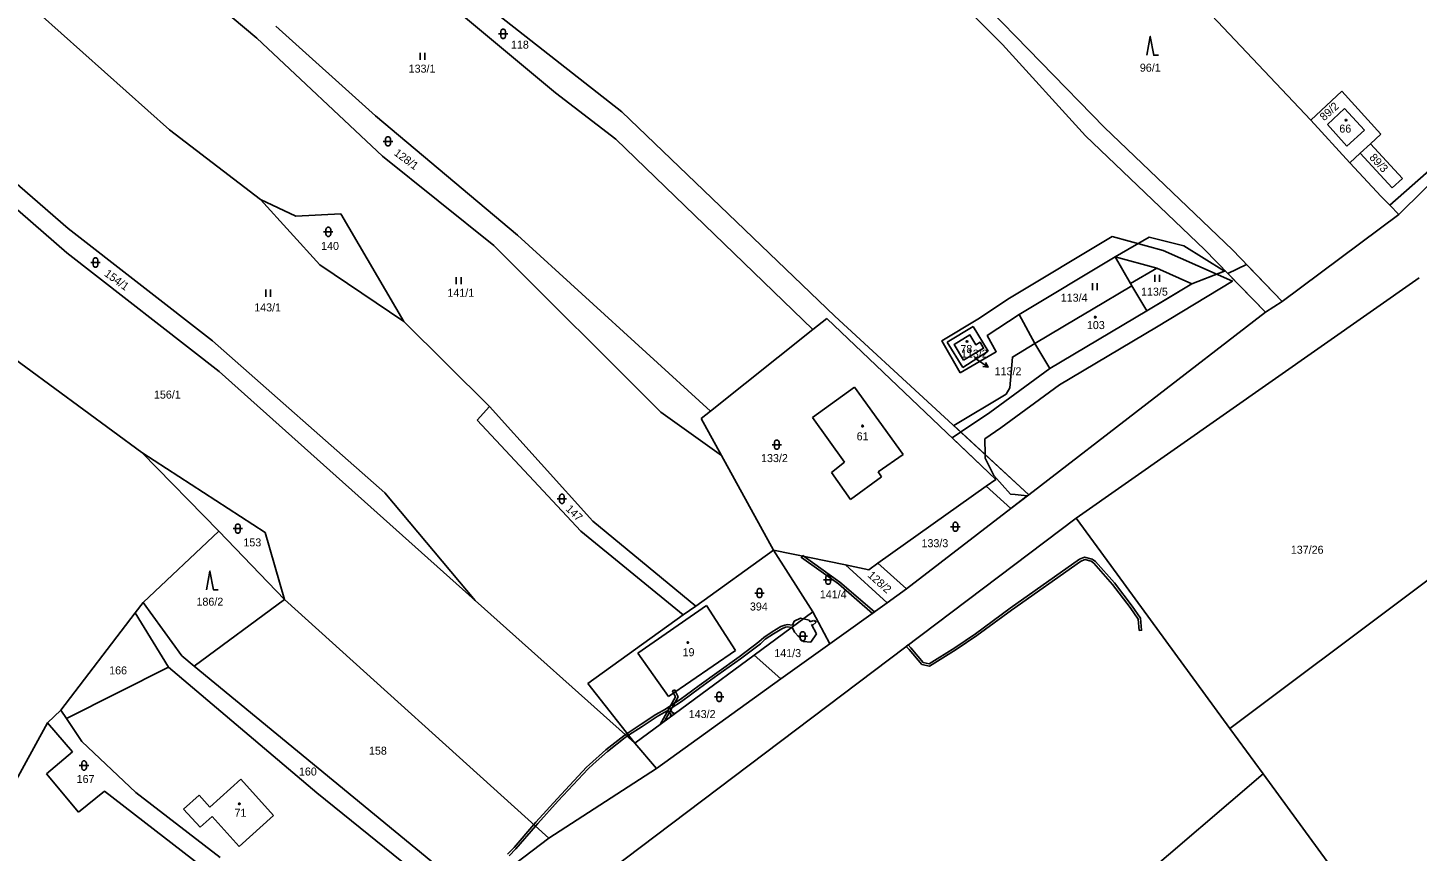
# Model space of a CAD drawing. Extents: x -811039 to -805820, y -1161436 to -1155864.
# Drawn here: x -807066.9 to -806771.7, y -1158370.8 to -1158195.9 of the extents above; entities that cross this region are included whole.
import ezdxf

# ---------------------------------------------------------------- set-up
doc = ezdxf.new("R2010")
doc.units = 0
for name, color, linetype in [('Default', 7, 'Continuous'), ('Hranice parcel', 7, 'Continuous'), ('Parcelní čísla', 7, 'Continuous'), ('Pop  PČ popisy', 7, 'Continuous'), ('Věcná břemena k části', 7, 'Continuous'), ('Značky budov', 7, 'Continuous'), ('Značky kultur', 7, 'Continuous')]:
    doc.layers.add(name, color=color, linetype=linetype)

# ---------------------------------------------------------------- blocks, each defined once
blk = doc.blocks.new('306')
at = {"layer": 'Default'}
for p, q in [((-0.5, 1.5), (-0.5, 0)), ((0.5, 0), (0.5, 1.5))]:
    blk.add_line(p, q, dxfattribs=at)
blk = doc.blocks.new('308')
at = {"layer": 'Default'}
blk.add_lwpolyline([(-0.75, 0), (0, 4), (0.75, 0), (1.75, 0)], dxfattribs=at)
blk = doc.blocks.new('316')
at = {"layer": 'Default'}
for points in [[(-1, 1), (0.27, 1), (1, 1)], [(-0.5, 1.5), (-0.4, 1.79), (-0.15, 1.97), (0.16, 1.97), (0.41, 1.79), (0.51, 1.5), (0.51, 0.5), (0.41, 0.21), (0.16, 0.03), (-0.15, 0.03), (-0.4, 0.21), (-0.5, 0.5), (-0.5, 1.5)]]:
    blk.add_lwpolyline(points, dxfattribs=at)
blk = doc.blocks.new('10292')
at = {"layer": 'Default'}
blk.add_line((0, 3), (0, 0), dxfattribs=at)
blk.add_lwpolyline([(-0.5, 2), (0, 3), (0.5, 2)], dxfattribs=at)
blk = doc.blocks.new('402')
at = {"layer": 'Default'}
blk.add_lwpolyline([(0.09, 0.15), (0.18, 0), (0.09, -0.15), (-0.09, -0.15), (-0.18, 0), (-0.09, 0.15), (0.09, 0.15)], dxfattribs=at)

msp = doc.modelspace()

# ---------------------------------------------------------------- linework, layer by layer
at = {"layer": 'Hranice parcel'}
for p, q in [((-807018.22, -1158198.03), (-807066.83, -1158157.18)), ((-806838.09, -1158217.06), (-806872.23, -1158182)), ((-806794.32, -1158215.46), (-806825.32, -1158182.62)), ((-806859.82, -1158199.37), (-806875.95, -1158183.18)), ((-807036.77, -1158217.51), (-807064.42, -1158192.88)), ((-806954.76, -1158209.69), (-806974.74, -1158193.03)), ((-806967.86, -1158192.42), (-806940.68, -1158213.7)), ((-807014.17, -1158195.54), (-806992.99, -1158214.58)), ((-806991.49, -1158223.13), (-807018.22, -1158198.03)), ((-806842.13, -1158218.84), (-806859.82, -1158199.37)), ((-806775.62, -1158235.5), (-806740.96, -1158201.43)), ((-806941.94, -1158219.49), (-806954.76, -1158209.69)), ((-806794.32, -1158215.46), (-806787.67, -1158209.35)), ((-806787.67, -1158209.35), (-806779.38, -1158218.47)), ((-806992.99, -1158214.58), (-806962.84, -1158239.91)), ((-806940.68, -1158213.7), (-806895.39, -1158257.1)), ((-806786.01, -1158224.54), (-806794.32, -1158215.46)), ((-806790.74, -1158216.43), (-806787.11, -1158212.99)), ((-806787.11, -1158212.99), (-806782.89, -1158217.6)), ((-807058.3, -1158238.51), (-807082.9, -1158217.2)), ((-807017.41, -1158232.31), (-807036.77, -1158217.51)), ((-806810.96, -1158243.02), (-806838.09, -1158217.06)), ((-806786.64, -1158220.97), (-806790.74, -1158216.43)), ((-806782.89, -1158217.6), (-806786.64, -1158220.97)), ((-806779.38, -1158218.47), (-806781.59, -1158220.49)), ((-806777.52, -1158233.56), (-806758.12, -1158216.37)), ((-807084.77, -1158220.97), (-807058.55, -1158243.68)), ((-806941.94, -1158219.49), (-806900.08, -1158259.94)), ((-806842.13, -1158218.84), (-806816.89, -1158242.94)), ((-806781.59, -1158220.49), (-806783.8, -1158222.51)), ((-806774.82, -1158227.88), (-806781.59, -1158220.49)), ((-806967.9, -1158242.14), (-806991.49, -1158223.13)), ((-806783.8, -1158222.51), (-806786.01, -1158224.54)), ((-806777.04, -1158229.89), (-806783.8, -1158222.51)), ((-806786.01, -1158224.54), (-806779.35, -1158231.7)), ((-807042.66, -1158286.07), (-807121.43, -1158228.14)), ((-806777.04, -1158229.89), (-806774.82, -1158227.88)), ((-807017.41, -1158232.31), (-807009.95, -1158235.89)), ((-807017.41, -1158232.31), (-807004.86, -1158246.24)), ((-806779.35, -1158231.7), (-806777.52, -1158233.56)), ((-807009.95, -1158235.89), (-807000.35, -1158235.36)), ((-806987.01, -1158258.28), (-807000.35, -1158235.36)), ((-806775.62, -1158235.5), (-806800.39, -1158254.02)), ((-806777.52, -1158233.56), (-806775.62, -1158235.5)), ((-807027.66, -1158262.37), (-807058.3, -1158238.51)), ((-806932.39, -1158277.49), (-806967.9, -1158242.14)), ((-806962.84, -1158239.91), (-806921.81, -1158277.3)), ((-807058.55, -1158243.68), (-807026.22, -1158268.84)), ((-806856.25, -1158256.75), (-806835.87, -1158244.53)), ((-806835.87, -1158244.53), (-806832.6, -1158250.2)), ((-806803.92, -1158256.3), (-806816.89, -1158242.94)), ((-806800.39, -1158254.02), (-806810.96, -1158243.02)), ((-807004.86, -1158246.24), (-806987.01, -1158258.28)), ((-806826.98, -1158246.94), (-806832.6, -1158250.2)), ((-806819.58, -1158250.22), (-806826.98, -1158246.94)), ((-806844.14, -1158300.03), (-806771.28, -1158248.97)), ((-806832.33, -1158250.66), (-806840.86, -1158255.74)), ((-806832.6, -1158250.2), (-806832.33, -1158250.66)), ((-806832.33, -1158250.66), (-806829.16, -1158256.01)), ((-806824.76, -1158253.35), (-806819.58, -1158250.22)), ((-806829.16, -1158256.01), (-806824.76, -1158253.35)), ((-806852.92, -1158262.92), (-806856.25, -1158256.75)), ((-806854.22, -1158295.07), (-806803.92, -1158256.3)), ((-806849.74, -1158268.26), (-806829.16, -1158256.01)), ((-806840.86, -1158255.74), (-806844, -1158257.61)), ((-806803.92, -1158256.3), (-806800.39, -1158254.02)), ((-806987.01, -1158258.28), (-806968.76, -1158276.34)), ((-806900.08, -1158259.94), (-806897.13, -1158257.59)), ((-806861.24, -1158291.79), (-806897.13, -1158257.59)), ((-806854.22, -1158295.07), (-806895.39, -1158257.1)), ((-806871.53, -1158262.63), (-806866.02, -1158259.28)), ((-806866.02, -1158259.28), (-806862.83, -1158264.59)), ((-806844, -1158257.61), (-806852.92, -1158262.92)), ((-806990.99, -1158294.65), (-807027.66, -1158262.37)), ((-806921.81, -1158277.3), (-806900.08, -1158259.94)), ((-806868.25, -1158268), (-806871.53, -1158262.63)), ((-806870.09, -1158263.14), (-806866.72, -1158261.12)), ((-806866.72, -1158261.12), (-806865.49, -1158263.19)), ((-806865.49, -1158263.19), (-806864.56, -1158262.65)), ((-806864.56, -1158262.65), (-806863.83, -1158263.95)), ((-806868.11, -1158266.45), (-806870.09, -1158263.14)), ((-806862.83, -1158264.59), (-806868.25, -1158268)), ((-806863.83, -1158263.95), (-806868.11, -1158266.45)), ((-806852.92, -1158262.92), (-806849.74, -1158268.26)), ((-806971.82, -1158317.52), (-807026.22, -1158268.84)), ((-806891.22, -1158272.18), (-806900.16, -1158278.66)), ((-806891.22, -1158272.18), (-806880.89, -1158286.52)), ((-806968.76, -1158276.34), (-806971.42, -1158279.21)), ((-806968.76, -1158276.34), (-806946.85, -1158300.67)), ((-806932.39, -1158277.49), (-806919.47, -1158286.75)), ((-806923.78, -1158278.88), (-806921.81, -1158277.3)), ((-806971.42, -1158279.21), (-806949.38, -1158302.82)), ((-806919.47, -1158286.75), (-806923.78, -1158278.88)), ((-806900.16, -1158278.66), (-806893.37, -1158288.16)), ((-807016.42, -1158303.1), (-807042.66, -1158286.07)), ((-807042.66, -1158286.07), (-807026.28, -1158302.83)), ((-806908.45, -1158306.85), (-806919.47, -1158286.75)), ((-806896.13, -1158290.31), (-806893.37, -1158288.16)), ((-806880.89, -1158286.52), (-806886.22, -1158290.18)), ((-806892.12, -1158296.04), (-806896.13, -1158290.31)), ((-806885.47, -1158291.24), (-806892.12, -1158296.04)), ((-806886.22, -1158290.18), (-806885.47, -1158291.24)), ((-806861.24, -1158291.79), (-806863.26, -1158293.22)), ((-806971.82, -1158317.52), (-806990.99, -1158294.65)), ((-806863.26, -1158293.22), (-806886.25, -1158309.58)), ((-806863.26, -1158293.22), (-806858.02, -1158298)), ((-806858.02, -1158298), (-806854.22, -1158295.07)), ((-806880.19, -1158315.08), (-806858.02, -1158298)), ((-806963.69, -1158390.26), (-806844.14, -1158300.03)), ((-806946.85, -1158300.67), (-806924.98, -1158318.71)), ((-806836.79, -1158310.08), (-806844.14, -1158300.03)), ((-807042.39, -1158317.98), (-807026.28, -1158302.83)), ((-807026.28, -1158302.83), (-807012.37, -1158317.33)), ((-807012.37, -1158317.33), (-807016.42, -1158303.1)), ((-806949.38, -1158302.82), (-806927.61, -1158320.6)), ((-806924.98, -1158318.71), (-806908.45, -1158306.85)), ((-806908.45, -1158306.85), (-806900.07, -1158319.96)), ((-806893.15, -1158309.97), (-806908.45, -1158306.85)), ((-806773.03, -1158315.88), (-806759.33, -1158305.54)), ((-806888.21, -1158310.98), (-806893.15, -1158309.97)), ((-806884.28, -1158318.02), (-806893.15, -1158309.97)), ((-806886.25, -1158309.58), (-806888.21, -1158310.98)), ((-806886.25, -1158309.58), (-806880.19, -1158315.08)), ((-806811.5, -1158344.69), (-806836.79, -1158310.08)), ((-806880.19, -1158315.08), (-806884.28, -1158318.02)), ((-806773.03, -1158315.88), (-806811.5, -1158344.69)), ((-807044.08, -1158320.18), (-807042.39, -1158317.98)), ((-807034.14, -1158329.27), (-807042.39, -1158317.98)), ((-807012.37, -1158317.33), (-807031.53, -1158331.51)), ((-806956.16, -1158368.04), (-807012.37, -1158317.33)), ((-806937.93, -1158347.83), (-806971.82, -1158317.52)), ((-806937.26, -1158328.73), (-806922.67, -1158318.61)), ((-806927.61, -1158320.6), (-806924.98, -1158318.71)), ((-806922.67, -1158318.61), (-806916.52, -1158328.12)), ((-806884.28, -1158318.02), (-806896.46, -1158326.7)), ((-807059.88, -1158340.81), (-807044.08, -1158320.18)), ((-807037, -1158331.69), (-807044.08, -1158320.18)), ((-806947.86, -1158335.13), (-806927.61, -1158320.6)), ((-806912.58, -1158329.17), (-806900.07, -1158319.96)), ((-806900.07, -1158319.96), (-806896.46, -1158326.7)), ((-806896.46, -1158326.7), (-806906.86, -1158334.2)), ((-807031.53, -1158331.51), (-807034.14, -1158329.27)), ((-806937.93, -1158347.83), (-806912.58, -1158329.17)), ((-806930.76, -1158337.94), (-806937.26, -1158328.73)), ((-806916.52, -1158328.12), (-806930.76, -1158337.94)), ((-806912.58, -1158329.17), (-806906.86, -1158334.2)), ((-807058.67, -1158342.57), (-807037, -1158331.69)), ((-807005.5, -1158358.42), (-807037, -1158331.69)), ((-807031.53, -1158331.51), (-806972.28, -1158380.19)), ((-806947.86, -1158335.13), (-806937.93, -1158347.83)), ((-806906.86, -1158334.2), (-806933.28, -1158353.24)), ((-807062.66, -1158343.51), (-807059.88, -1158340.81)), ((-807059.88, -1158340.81), (-807058.67, -1158342.57)), ((-807074.55, -1158365.1), (-807062.66, -1158343.51)), ((-807062.66, -1158343.51), (-807057.38, -1158349.64)), ((-807058.67, -1158342.57), (-807055.43, -1158347.48)), ((-806804.42, -1158354.37), (-806811.5, -1158344.69)), ((-807055.43, -1158347.48), (-807043.91, -1158358.31)), ((-806937.93, -1158347.83), (-806933.28, -1158353.24)), ((-807057.38, -1158349.64), (-807062.93, -1158354.38)), ((-806956.16, -1158368.04), (-806933.28, -1158353.24)), ((-807062.93, -1158354.38), (-807056.14, -1158362.46)), ((-807021.65, -1158355.47), (-807028.2, -1158361.44)), ((-807014.67, -1158363.18), (-807021.65, -1158355.47)), ((-806911.61, -1158445.88), (-806804.42, -1158354.37)), ((-806804.42, -1158354.37), (-806771.88, -1158398.73)), ((-807056.14, -1158362.46), (-807050.56, -1158358.04)), ((-807050.56, -1158358.04), (-806998.39, -1158398.35)), ((-807026.03, -1158372.13), (-807043.91, -1158358.31)), ((-807030.5, -1158358.9), (-807033.81, -1158361.83)), ((-807028.2, -1158361.44), (-807030.5, -1158358.9)), ((-806975.45, -1158382.58), (-807005.5, -1158358.42)), ((-807033.81, -1158361.83), (-807030.27, -1158365.71)), ((-807021.99, -1158369.8), (-807014.67, -1158363.18)), ((-807030.27, -1158365.71), (-807027.74, -1158363.42)), ((-807027.74, -1158363.42), (-807021.99, -1158369.8)), ((-806972.28, -1158380.19), (-806956.16, -1158368.04))]:
    msp.add_line(p, q, dxfattribs=at)
at = {"layer": 'Pop  PČ popisy'}
msp.add_line((-806865.72, -1158265.93), (-806865.29, -1158266.24), dxfattribs=at)
at = {"layer": 'Věcná břemena k části'}
for p, q in [((-806904.43, -1158322.8), (-806904.06, -1158321.88)), ((-806904.06, -1158321.88), (-806902.7, -1158321.3)), ((-806902.7, -1158321.3), (-806902.08, -1158321.44)), ((-806902.08, -1158321.44), (-806900.86, -1158321.72)), ((-806900.86, -1158321.72), (-806900.67, -1158322.07)), ((-806900.67, -1158322.07), (-806899.92, -1158321.75)), ((-806899.92, -1158321.75), (-806899.85, -1158321.9)), ((-806899.85, -1158321.9), (-806899.68, -1158321.75)), ((-806899.68, -1158321.75), (-806899.35, -1158322.12)), ((-806910.5, -1158325.36), (-806908.71, -1158324.19)), ((-806908.43, -1158324.6), (-806910.2, -1158325.76)), ((-806908.71, -1158324.19), (-806906.9, -1158323.06)), ((-806906.67, -1158323.51), (-806908.43, -1158324.6)), ((-806906.9, -1158323.06), (-806906.05, -1158322.73)), ((-806905.92, -1158323.21), (-806906.67, -1158323.51)), ((-806906.05, -1158322.73), (-806905.47, -1158322.65)), ((-806905.47, -1158323.15), (-806905.92, -1158323.21)), ((-806905.47, -1158322.65), (-806904.43, -1158322.8)), ((-806904.58, -1158323.28), (-806905.47, -1158323.15)), ((-806904.44, -1158323.3), (-806904.58, -1158323.28)), ((-806903.97, -1158324.24), (-806904.44, -1158323.3)), ((-806902.11, -1158326.26), (-806903.97, -1158324.24)), ((-806899.3, -1158324.62), (-806900.5, -1158326.39)), ((-806900.1, -1158322.78), (-806900.39, -1158322.6)), ((-806900.39, -1158322.6), (-806899.3, -1158324.62)), ((-806899.35, -1158322.12), (-806900.1, -1158322.78)), ((-806915.72, -1158329.51), (-806911.53, -1158326.34)), ((-806911.21, -1158326.72), (-806915.45, -1158329.93)), ((-806911.53, -1158326.34), (-806910.5, -1158325.36)), ((-806910.2, -1158325.76), (-806911.21, -1158326.72)), ((-806900.5, -1158326.39), (-806902.11, -1158326.26)), ((-806920.48, -1158332.89), (-806915.72, -1158329.51)), ((-806915.45, -1158329.93), (-806920.24, -1158333.33)), ((-806924.24, -1158335.6), (-806920.48, -1158332.89)), ((-806920.24, -1158333.33), (-806924.16, -1158336.16)), ((-806928.28, -1158338.53), (-806924.24, -1158335.6)), ((-806924.16, -1158336.16), (-806928.02, -1158338.96)), ((-806930.49, -1158339.99), (-806928.28, -1158338.53)), ((-806928.02, -1158338.96), (-806930.17, -1158340.38)), ((-806936.53, -1158343.79), (-806933.42, -1158341.76)), ((-806933.15, -1158342.18), (-806936.37, -1158344.28)), ((-806933.42, -1158341.76), (-806931.4, -1158340.58)), ((-806931.15, -1158341.02), (-806933.15, -1158342.18)), ((-806931.4, -1158340.58), (-806930.49, -1158339.99)), ((-806930.91, -1158341.03), (-806931.15, -1158341.02)), ((-806930.64, -1158341.2), (-806930.91, -1158341.03)), ((-806930.2, -1158341.82), (-806930.64, -1158341.2)), ((-806930.4, -1158341.96), (-806930.2, -1158341.82)), ((-806930.25, -1158342.18), (-806930.4, -1158341.96)), ((-806930.17, -1158340.38), (-806930.3, -1158340.64)), ((-806930.3, -1158340.64), (-806930.23, -1158340.91)), ((-806929.45, -1158341.59), (-806930.25, -1158342.18)), ((-806930.23, -1158340.91), (-806929.79, -1158341.54)), ((-806929.79, -1158341.54), (-806929.58, -1158341.4)), ((-806929.58, -1158341.4), (-806929.45, -1158341.59)), ((-806939.54, -1158345.77), (-806936.53, -1158343.79)), ((-806936.37, -1158344.28), (-806939.24, -1158346.16)), ((-806944.07, -1158349.25), (-806940.28, -1158346.25)), ((-806939.99, -1158346.65), (-806943.75, -1158349.63)), ((-806940.28, -1158346.25), (-806939.94, -1158346.03)), ((-806939.56, -1158346.37), (-806939.99, -1158346.65)), ((-806939.94, -1158346.03), (-806939.54, -1158345.77)), ((-806939.24, -1158346.16), (-806939.56, -1158346.37)), ((-806939.24, -1158346.16), (-806939.54, -1158345.77)), ((-806939.54, -1158345.77), (-806939.24, -1158346.16)), ((-806947.57, -1158352.35), (-806944.07, -1158349.25)), ((-806943.75, -1158349.63), (-806946.73, -1158352.27)), ((-806954.42, -1158359.64), (-806948.21, -1158352.92)), ((-806947.85, -1158353.26), (-806954.18, -1158360.12)), ((-806948.21, -1158352.92), (-806947.57, -1158352.35)), ((-806946.73, -1158352.27), (-806947.85, -1158353.26)), ((-806958.95, -1158364.61), (-806954.42, -1158359.64)), ((-806954.18, -1158360.12), (-806958.55, -1158364.91)), ((-806963.56, -1158369.98), (-806959.39, -1158365.12)), ((-806959.02, -1158365.46), (-806963.17, -1158370.29)), ((-806959.39, -1158365.12), (-806958.95, -1158364.61)), ((-806959.39, -1158365.12), (-806959.02, -1158365.46)), ((-806959.02, -1158365.46), (-806959.39, -1158365.12)), ((-806958.55, -1158364.91), (-806959.02, -1158365.46)), ((-806964.93, -1158371.42), (-806963.56, -1158369.98)), ((-806963.17, -1158370.29), (-806964.59, -1158371.79))]:
    msp.add_line(p, q, dxfattribs=at)
for points in [[(-806868.81, -1158269.18), (-806872.65, -1158262.34), (-806865.01, -1158257.76), (-806858.31, -1158253.32), (-806836.47, -1158240.22), (-806825.64, -1158243.16), (-806810.94, -1158249.67), (-806827.1, -1158259.44), (-806847.69, -1158271.7), (-806860.15, -1158280.81), (-806863.56, -1158283.18), (-806863.49, -1158286.52), (-806863.47, -1158287.27), (-806861.64, -1158290.99), (-806858.08, -1158294.91), (-806857.1, -1158295.02), (-806854.55, -1158295.32), (-806858.02, -1158298), (-806863.26, -1158293.22), (-806861.24, -1158291.79), (-806870.47, -1158283), (-806868.69, -1158281.73), (-806862.47, -1158277.55), (-806849.74, -1158268.26), (-806829.16, -1158256.01), (-806824.76, -1158253.35), (-806819.58, -1158250.22), (-806826.98, -1158246.94), (-806835.87, -1158244.53), (-806856.25, -1158256.75), (-806863.05, -1158261.26), (-806861.12, -1158264.69)], [(-806835.87, -1158244.53), (-806828.64, -1158240.34), (-806821.26, -1158242.2), (-806812.63, -1158247.54), (-806819.58, -1158250.22), (-806826.98, -1158246.94), (-806832.6, -1158250.2)], [(-806870.16, -1158280.37), (-806859, -1158273.69), (-806858.24, -1158272.34), (-806857.68, -1158265.81), (-806852.92, -1158262.92), (-806849.74, -1158268.26), (-806829.16, -1158256.01), (-806819.58, -1158250.22), (-806812.48, -1158247.48), (-806803.92, -1158256.3), (-806854.22, -1158295.07)], [(-806811.89, -1158248.09), (-806807.98, -1158246.12), (-806800.39, -1158254.02), (-806803.92, -1158256.3)], [(-806868.11, -1158266.45), (-806863.83, -1158263.95), (-806864.56, -1158262.65), (-806865.49, -1158263.19), (-806866.72, -1158261.12), (-806870.09, -1158263.14)], [(-806887.42, -1158320.26), (-806894.64, -1158314.01), (-806902.5, -1158308.39), (-806902.3, -1158308.1), (-806902.21, -1158307.98), (-806901.93, -1158308.18), (-806894.33, -1158313.61), (-806887, -1158319.96)], [(-806879.84, -1158326.97), (-806879.27, -1158327.56), (-806876.65, -1158330.68), (-806875.4, -1158330.95), (-806869.91, -1158327.55), (-806865.53, -1158324.58), (-806858.17, -1158319.17), (-806843.47, -1158308.77), (-806842.37, -1158308.32), (-806840.74, -1158308.72), (-806840.02, -1158309.23), (-806836.02, -1158313.78), (-806832.26, -1158318.7), (-806830.48, -1158321.29), (-806830.23, -1158323.85), (-806830.73, -1158323.89), (-806830.96, -1158321.47), (-806832.66, -1158319), (-806836.4, -1158314.1), (-806840.36, -1158309.61), (-806840.96, -1158309.18), (-806842.33, -1158308.84), (-806843.23, -1158309.21), (-806857.87, -1158319.57), (-806865.25, -1158324.98), (-806869.63, -1158327.97), (-806875.3, -1158331.49), (-806876.93, -1158331.14), (-806879.65, -1158327.9), (-806880.24, -1158327.28)], [(-806929.43, -1158336.5), (-806929.24, -1158336.89), (-806928.72, -1158337.99), (-806931.58, -1158343.15), (-806932.54, -1158343.86), (-806929.28, -1158337.97), (-806929.66, -1158337.18), (-806929.88, -1158336.72)]]:
    msp.add_lwpolyline(points, close=True, dxfattribs=at)

# ---------------------------------------------------------------- block references
at = {"layer": 'Pop  PČ popisy', "rotation": -125.54567000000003}
msp.add_blockref('10292', (-806865.29, -1158266.24), dxfattribs=at)
at = {"layer": 'Značky budov'}
for p in [(-806786.81, -1158215.5), (-806840.09, -1158257.34), (-806867.35, -1158262.48), (-806889.53, -1158280.45), (-806926.64, -1158326.47), (-807021.92, -1158360.74)]:
    msp.add_blockref('402', p, dxfattribs=at)
at = {"layer": 'Značky kultur'}
for name, p in [('316', (-806965.88, -1158198.14)), ('308', (-806828.4, -1158201.68)), ('306', (-806983.05, -1158202.68)), ('316', (-806990.35, -1158220.98)), ('316', (-807003.04, -1158240.19)), ('316', (-807052.51, -1158246.73)), ('306', (-806975.34, -1158250.31)), ('306', (-806840.15, -1158251.62)), ('306', (-806826.94, -1158249.83)), ('306', (-807015.8, -1158252.98)), ('316', (-806907.76, -1158285.42)), ('316', (-806953.4, -1158296.93)), ('316', (-806869.81, -1158302.86)), ('316', (-807022.26, -1158303.25)), ('308', (-807028.17, -1158315.28)), ('316', (-806896.84, -1158314.1)), ('316', (-806911.42, -1158316.95)), ('316', (-806902.25, -1158326.13)), ('316', (-806920.01, -1158338.99)), ('316', (-807054.93, -1158353.59))]:
    msp.add_blockref(name, p, dxfattribs=at)

# ---------------------------------------------------------------- texts
at = {"layer": 'Parcelní čísla'}
for s, p in [('118', (-806964.22, -1158200.29)), ('133/1', (-806985.96, -1158205.38)), ('96/1', (-806830.61, -1158205.18)), ('66', (-806788.23, -1158218.12)), ('140', (-807004.56, -1158243.05)), ('113/5', (-806830.36, -1158252.76)), ('141/1', (-806977.73, -1158253.01)), ('113/4', (-806847.42, -1158254.04)), ('143/1', (-807018.77, -1158256.11)), ('103', (-806841.86, -1158259.86)), ('78', (-806868.74, -1158264.94)), ('113/2', (-806868.62, -1158265.93)), ('113/2', (-806861.46, -1158269.68)), ('156/1', (-807040.07, -1158274.63)), ('61', (-806890.78, -1158283.5)), ('133/2', (-806911.09, -1158288.12)), ('153', (-807021.07, -1158306.03)), ('133/3', (-806877, -1158306.2)), ('137/26', (-806798.54, -1158307.59)), ('141/4', (-806898.6, -1158317.06)), ('186/2', (-807031.04, -1158318.63)), ('394', (-806913.46, -1158319.65)), ('19', (-806927.76, -1158329.36)), ('141/3', (-806908.28, -1158329.55)), ('166', (-807049.59, -1158333.22)), ('143/2', (-806926.45, -1158342.5)), ('158', (-806994.39, -1158350.28)), ('160', (-807009.27, -1158354.71)), ('167', (-807056.5, -1158356.29)), ('71', (-807022.96, -1158363.46))]:
    msp.add_text(s, height=1.7, dxfattribs=at).set_placement(p)
for s, rotation, p in [('89/2', 42.456, (-806791.45, -1158215.74)), ('128/1', 323.377, (-806989.24, -1158222.76)), ('89/3', 313.064, (-806781.97, -1158223.52)), ('154/1', 323.836, (-807050.77, -1158248.42)), ('147', 316.044, (-806952.74, -1158298.23)), ('128/2', 318.163, (-806888.58, -1158312.35))]:
    msp.add_text(s, height=1.7, rotation=rotation, dxfattribs=at).set_placement(p)

doc.saveas('drawing.dxf')
